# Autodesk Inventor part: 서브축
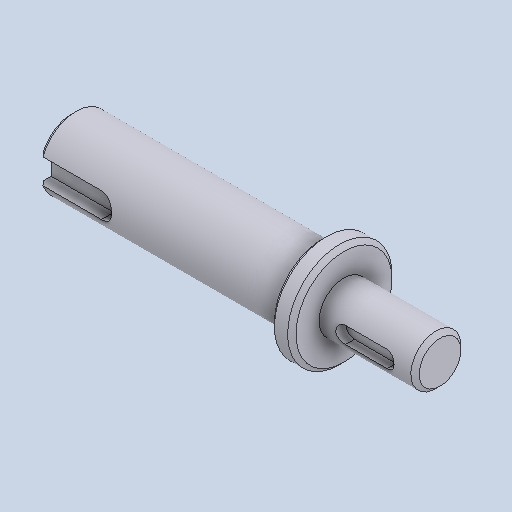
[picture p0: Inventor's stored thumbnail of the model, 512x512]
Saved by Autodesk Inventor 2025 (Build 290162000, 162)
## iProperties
Created: 2024-08
Part Number: 서브축
Material: 강철, 연강
Document SubType Name: Modeling
Designer: rese9
Density: 7.86 g/cm^3
Appearance: 기본값
Author: jhkim
Sending System: Autodesk Inventor 2025
Preprocessor: ST-DEVELOPER v20
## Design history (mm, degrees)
feature "솔리드1"
node "솔리드2"
